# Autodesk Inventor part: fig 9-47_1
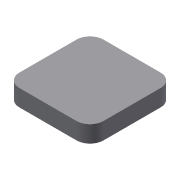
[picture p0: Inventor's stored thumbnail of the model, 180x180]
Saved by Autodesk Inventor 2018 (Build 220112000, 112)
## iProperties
Created: 2013-03
Part Number: fig 9-47_1
Material: Generic
Document SubType Name: Modeling
Designer: CADCIM
Density: 1 g/cm^3
Appearance: Default
Author: CADCIM
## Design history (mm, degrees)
sketch "Sketch1"
  geometry: L1 (-12.5, 12.5)-(12.5, 12.5); L2 (12.5, 12.5)-(12.5, -12.5); L3 (12.5, -12.5)-(-12.5, -12.5); L4 (-12.5, -12.5)-(-12.5, 12.5); 1 further point
  constraints: 8 end point, 2 parallel, 1 horizontal, 1 perpendicular
  dimensions: "d0" = 25 distance of L1.start L1.end; "d2" = 25 distance of L1.end L2.end
extrude "Extrusion1" new body sketch "Sketch1" distance "d3" = 5; taper "d4" = 0 deg
fillet "Fillet1" dims "d5" = 4
body "Solid1"
